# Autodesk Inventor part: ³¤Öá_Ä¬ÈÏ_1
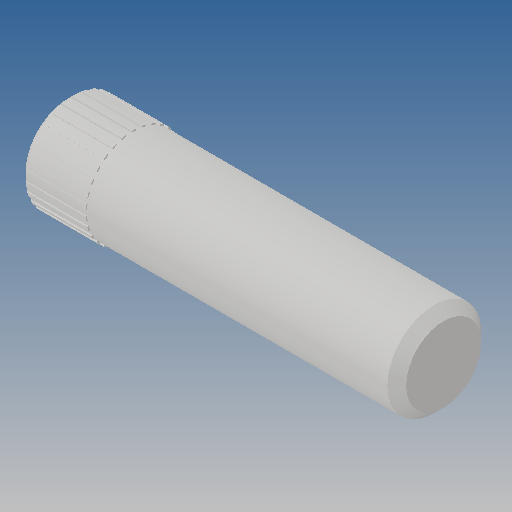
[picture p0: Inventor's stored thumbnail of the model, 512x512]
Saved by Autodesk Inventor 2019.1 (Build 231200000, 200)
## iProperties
Created: 2012-10
Part Number: ³¤Öá_Ä¬ÈÏ_1
Material: Ogólny
Document SubType Name: Modeling
Designer: CADENGINEERING4
Density: 1 g/cm^3
Appearance: Domyślna
Author: CADENGINEERING4
Revision Number: ÈÎºÎ
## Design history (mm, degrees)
feature "NONE"
node "Bryła1"
